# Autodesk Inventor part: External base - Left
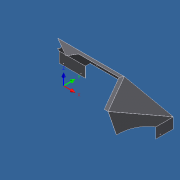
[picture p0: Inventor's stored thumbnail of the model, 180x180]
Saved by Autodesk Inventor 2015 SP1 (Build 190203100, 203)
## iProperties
Category: Mechanical Engineering Drawing and Design - CADD
Manager: Fábio Ricardo de Oliveira Souza
Company: SENAI - Serviço Nacional de Aprendizagem Industrial
Created: 2011-06
Part Number: External base - Left
Material: Steel
Description: Stainless Steel (DIN- X6CrNiTi18-10)
Document SubType Name: Sheet Metal
Designer: Guilherme Augusto Franco de Souza
Engineer: George Geraldo de Oliveia Silva
Authority: Fábio Ricardo de Oliveira Soza
Density: 7.85 g/cm^3
Sheet Metal Rule: Default_mm
Sheet Metal Width: 0,000 mm
Sheet Metal Length: 0,000 mm
Sheet Metal Area: 0,000 mm^2
Appearance: Machined 02
Subject: WorldSkill 2011 - London, England
Author: Guilherme Augusto Franco de Souza
Revision Number: 00
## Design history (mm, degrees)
sketch "Sketch1"
  geometry: L1 (-253, 219.104)-(-253, -219.104); L2 (-253, -219.104)-(126.5, -219.104); L3 (126.5, -219.104)-(253, 0); L4 (253, 0)-(126.5, 219.104); L5 (-253, 219.104)-(126.5, 219.104); L6 (-230.94, 0)-(-115.47, 200); L7 (-115.47, 200)-(115.47, 200); L8 (115.47, 200)-(230.94, 0); L9 (230.94, 0)-(115.47, -200); L10 (115.47, -200)-(-115.47, -200); L11 (-115.47, -200)-(-230.94, 0); A1 r 253 centre (0, 0) between (126.5, -219.104) and (253, 0); 2 further points
  constraints: 22 end point, 3 point on circle, 2 coincident, 2 horizontal alignment, 2 parallel, 1 centre point, 1 equal length, 1 perpendicular, 1 tangent, 1 vertical, 13 other
  dimensions: "d0" = 506 diameter of A1; "d1" = 200 distance from line of point (0, 0) L10
patch "Boundary Patch1" sketch "Sketch1"
sketch "Sketch2"
  geometry: L1 (-219.104, 0)-(-300, -140.115); L2 (-300, -140.115)-(-300, -200); 2 further points
  constraints: 4 end point, 1 vertical
  dimensions: "d3" = 30 deg angle of L2 L1; "d4" = 300 distance from line of point (0, 0) L2; "d26" = 200 vertical distance of point (0, 0) L2.end
extrude_surface "ExtrusionSrf1" sketch "Sketch2" dims "d5" = 650, "d6" = 0
mirror "Mirror1"
sketch "Sketch3"
  geometry: L1 (325, -140.115)-(325, -200) reference; L2 (325, -120)-(325, -140.115); A1 r 136 centre (389, 0) between (253, 0) and (325, -120); 1 further point
  constraints: 2 end point, 2 point on circle, 1 centre point, 1 collinear, 1 horizontal alignment, 1 vertical alignment
  dimensions: "d7" = 120 vertical distance of A1.start L2.start
extrude_surface "ExtrusionSrf3" sketch "Sketch3" dims "d8" = 600, "d9" = 0
feature "Trim1"
feature "Trim2"
feature "Trim3"
feature "Trim4"
sketch "Sketch4"
  geometry: L1 (-325, -200)-(-325, -140.115) reference; L2 (-325, -140.115)-(-253, 0); 1 further point
  constraints: 2 end point
extrude_surface "ExtrusionSrf4" sketch "Sketch4" dims "d10" = 600, "d11" = 0
workplane "Work Plane1"
feature "Trim5"
feature "Trim6"
workplane "Work Plane2"
feature "Trim7"
feature "Trim8"
patch "Boundary Patch2" dims "d12" = 0, "d13" = 0, "d14" = 0, "d15" = 0
patch "Boundary Patch3" dims "d16" = 0, "d17" = 0, "d18" = 0, "d19" = 0
sketch "Sketch5"
  geometry: L1 (-200, -200)-(-200, -140); L2 (200, -200)-(200, -140); L3 (-300, -200)-(300, -200) reference; A1 r 440.667 centre (0, -532.667) between (200, -140) and (-200, -140); 1 further point
  constraints: 4 end point, 2 parallel, 2 point on circle, 1 centre point, 1 horizontal alignment, 1 point on line, 1 vertical, 1 vertical alignment
  dimensions: "d21" = 60 distance of L1.start L1.end; "d22" = 400 distance between parallel lines of L2 L1; "d23" = 108 distance edge to line of A1 L3
extrude_surface "ExtrusionSrf5" sketch "Sketch5" dims "d24" = 600, "d25" = 0
feature "Trim9"
feature "Stitch Surface1"
sketch "Sketch16"
  geometry: L1 (176, -200)-(176, -140); L2 (176, -140)-(111, -75); L3 (111, -75)-(-111, -75); L4 (-111, -75)-(-176, -140); L5 (-176, -140)-(-176, -200); L6 (325, -200)-(-325, -200) reference; 1 further point
  constraints: 10 end point, 2 equal length, 1 horizontal alignment, 1 parallel, 1 perpendicular, 1 point on line, 1 vertical
  dimensions: "d68" = 352 distance between parallel lines of L5 L1; "d69" = 176 distance from line of point (0, 0) L1 (= 0.5 x d68); "d70" = 125 distance between parallel lines of L6 L3; "d71" = 60 distance of L4.end L5.end; "d72" = 222 distance of L2.end L3.end
extrude_surface "ExtrusionSrf6" sketch "Sketch16" dims "d73" = 600, "d74" = 0
feature "Trim10"
feature "Trim11"
sketch "Sketch19"
  geometry: L1 (126.5, -218.854)-(-232.948, -218.854); L2 (-232.948, -218.854)-(-232.948, -219.354); L3 (-232.948, -219.354)-(126.5, -219.354); L4 (126.5, -219.354)-(126.5, -218.854); 2 further points
  constraints: 8 end point, 2 parallel, 1 coincident, 1 horizontal, 1 midpoint, 1 perpendicular
  dimensions: "d102" = 0.5 distance of L3.end L1.start
extrude_surface "ExtrusionSrf7" sketch "Sketch19" dims "d103" = 200, "d104" = 0
feature "Trim12"
sketch "Sketch20"
  geometry: L1 (357.44, 219.104)-(241.97, 419.104) reference; L2 (379.5, 438.209)-(268.08, 373.881); 1 further point
  constraints: 2 end point, 1 perpendicular, 1 point on line
extrude_surface "ExtrusionSrf8" sketch "Sketch20" dims "d105" = 10, "d106" = 0
sketch "Sketch21"
  geometry: L1 (241.97, 19.104)-(357.44, 219.104) reference; L2 (379.5, 0)-(268.08, 64.328); 1 further point
  constraints: 2 end point, 1 perpendicular, 1 point on line
extrude_surface "ExtrusionSrf9" sketch "Sketch21" dims "d107" = 10, "d108" = 0
split "Split2"
split "Split3"
fillet "Fillet2" dims "d113" = 1.25
fillet "Fillet3" dims "d114" = 1.25
delete_face "Delete Face3"
delete_face "Delete Face4"
delete_face "Delete Face5"
delete_face "Delete Face6"
delete_face "Delete Face7"
feature "Trim13"
delete_face "Delete Face8"
thicken "Thicken2" dims "d115" = 1
feature "Rip14" dims "d116" = 1 (= GapSize)
feature "Rip15" dims "d117" = 0.5 (= 0.5 x GapSize)
node "Unfold1"
delete_face "Delete Face9"
sketch "Sketch24"
  geometry: L1 (438.019, -69.739)-(437.721, -69.602) reference; L2 (418.516, 262.221)-(418.381, 261.929) reference; L3 (435.347, -69.117)-(434.91, -69.14) reference; L4 (434.91, -69.14)-(417.944, 261.907) reference; L5 (432.329, -72.17)-(431.956, -72.628) reference; L6 (431.956, -72.628)-(237.483, 85.881) reference; L7 (431.248, -74.854)-(431.248, -75.215) reference; L8 (434.75, -134.765)-(434.75, -74.017) reference; L9 (435.129, -69.129)-(435.432, -75.034); L10 (431.248, -75.034)-(435.432, -75.034); L11 (437.87, -69.67)-(434.046, -77.958); L12 (432.143, -72.399)-(437.721, -76.946); C1 r 1.5 at (434.75, -74.017); 1 further point
  constraints: 8 end point, 4 midpoint, 3 parallel, 1 centre point, 1 coincident, 1 perpendicular
  dimensions: "d119" = 3 diameter of C1
cut "Cut10" sketch "Sketch24" dims "d120" = 1 (= Thickness), "d121" = 0
sketch "Sketch25"
  geometry: L1 (417.944, 261.907)-(237.856, 86.338) reference; L2 (237.483, 85.881)-(-140.756, 85.881) reference; L3 (-140.75, 86.603)-(237.192, 86.603) reference; L4 (237.78, 86.826)-(417.663, 262.195) reference; L5 (236.014, 86.242)-(237.469, 86.242); L6 (238.561, 87.306)-(237.469, 86.242); L7 (237.856, 86.338)-(432.329, -72.17) reference; L8 (431.956, -72.628)-(237.483, 85.881) reference; L9 (232.162, 107.506)-(237.78, 86.826) reference; L10 (237.192, 86.603)-(226.179, 104.986) reference; L11 (237.192, 86.603)-(238.343, 84.682); L12 (238.176, 85.697)-(237.487, 86.259); C1 r 1.5 at (237.487, 86.259); 1 further point
  constraints: 8 end point, 3 parallel, 1 centre point, 1 coincident, 1 collinear, 1 point on line
  dimensions: "d122" = 0.72257 distance between parallel lines of L3 L2 (derived); "d123" = 0.36128 distance between parallel lines of L3 L5 (= 0.5 x d122); "d124" = 0.40244 distance between parallel lines of L4 L1 (derived); "d127" = 0.20122 distance between parallel lines of L1 L6 (= 0.5 x d124); "d131" = 3 diameter of C1; "d132" = 0.59032 distance between parallel lines of L7 L8 (derived); "d133" = 0.29516 distance between parallel lines of L7 L12 (= 0.5 x d132)
cut "Cut11" sketch "Sketch25" dims "d129" = 1 (= Thickness), "d130" = 0
sketch "Sketch26"
  geometry: L1 (418.381, 261.929)-(435.347, -69.117) reference; L2 (434.91, -69.14)-(417.944, 261.907) reference; L3 (417.944, 261.907)-(238.691, 87.153) reference; L4 (238.411, 87.441)-(417.663, 262.195) reference; L5 (417.331, 261.59)-(418.139, 262.378); L6 (418.2, 261.193)-(418.139, 262.378); C1 r 1.5 at (418.139, 262.378); 1 further point
  constraints: 4 end point, 2 parallel, 1 centre point, 1 coincident
  dimensions: "d134" = 0.40244 distance between parallel lines of L4 L3 (derived); "d135" = 0.20122 distance between parallel lines of L4 L5 (= 0.5 x d134); "d136" = 0.43741 distance between parallel lines of L1 L2 (derived); "d137" = 0.2187 distance between parallel lines of L1 L6 (= 0.5 x d136); "d138" = 3 diameter of C1
cut "Cut12" sketch "Sketch26" dims "d139" = 1 (= Thickness), "d140" = 0
node "Refold1"
node "Refold2"
sketch "Sketch27"
  geometry: L1 (0, 55.55)-(0, 0) reference; L2 (149, 55.258)-(149, -4) reference; L3 (24.5, 7)-(124.5, 7); L4 (-499.75, -4)-(-352, -4) reference; L5 (-352, -4)-(-352, 55.55) reference; 6 further points; 1 other entity
  constraints: 2 end point, 2 horizontal alignment, 1 midpoint, 1 other
  dimensions: "d147" = 11 dimension on L3.end; "d148" = 100 distance of L3.start L3.end; "d149" = 24.5 distance from line of L1 L3.start; "d150" = 11 distance from line of L4 point (-376.5, 7); "d151" = 100 distance of point (-476.5, 7) point (-376.5, 7); "d152" = 24.5 distance from line of point (-376.5, 7) L5
hole "Hole4" sketch "Sketch27" at (124.5, 7), (24.5, 7), (-376.5, 7), (-476.5, 7) diameter "d153" = 3.3; stored, may be unused: countersink angle "d157" = 90 deg, drill point angle "d159" = 118 deg; dims "d154" = 6, "d155" = 4, "d156" = 2, "d158" = 1 (derived)
sketch "Sketch28"
  geometry: L1 (55.582, 0)-(0, 0) reference; 4 further points; 1 other entity
  constraints: 1 other
  dimensions: "d160" = 11 dimension on point (7, -25); "d161" = 25 distance from line of L1 point (7, -25)
hole "Hole5" sketch "Sketch28" at (7, -25) diameter "d162" = 3.3; stored, may be unused: countersink angle "d166" = 90 deg, drill point angle "d168" = 118 deg; dims "d163" = 6, "d164" = 4, "d165" = 2, "d167" = 1 (derived)
mirror "Mirror6"
node "Hole1"
node "Hole2"
body "Solid2"
body "Srf1"
body "Srf2"
body "Srf3"
body "Srf4"
body "Srf5"
body "Srf6"
body "Srf7"
body "Srf8"
body "Srf9"
body "Srf10"
body "Srf11"
body "Srf12"
body "Srf13"
sketch "Sketch29"
  geometry: 1 further point
hole "Hole6" sketch "Sketch29" diameter "d169" = 3.4; stored, may be unused: countersink angle "d173" = 90 deg, drill point angle "d175" = 0 deg; dims "d170" = 6, "d171" = 4, "d172" = 2, "d174" = 8
sketch "Sketch30"
  geometry: 1 further point
hole "Hole7" sketch "Sketch30" diameter "d176" = 3.4; stored, may be unused: countersink angle "d180" = 90 deg, drill point angle "d182" = 0 deg; dims "d177" = 6, "d178" = 4, "d179" = 2, "d181" = 8
extrude_surface "ExtrusionSrf2"
other parameters: "Thickness" = 1 (derived), "BendRadius" = 1 (= Thickness), "BendReliefWidth" = 1 (= Thickness), "BendReliefDepth" = 0.5 (= 0.5 x Thickness), "CornerReliefSize" = 4 (= 4 x Thickness), "SeamGap" = 0.01, "MinimumRemnant" = 2 (= 2 x Thickness), "TransitionRadius" = 1 (= BendRadius), "JacobiRadiusSize" = 1 (= BendRadius), "GapSize" = 1 (= Thickness), "d141" = 0, "d142" = 0, "d143" = 0, "d144" = 0, "d145" = 0, "d146" = 0
